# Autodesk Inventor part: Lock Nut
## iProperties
Shininess: 77.0
Length Units: 11269
Angle Units: 11279
Time Units: 11290
Mass Units: 11283
Length Display Precision: 3
Angle Display Precision: 2
Created: 2002-02
Part Number: Lock Nut
Document SubType Name: Modeling
Designer: ***
Density: 0.0
Volumn: 0.0
Area: 0.0
PropertySet Name: Model Information
Control State: 0
Master: False
Checked Out: False
Author: ***
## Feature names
1. Extrusion1
2. Fillet1
3. Extrusion2
4. Hole1
